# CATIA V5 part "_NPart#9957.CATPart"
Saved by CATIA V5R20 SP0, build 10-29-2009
Part number: Junta tórica Ø12x1
Revision: ANY
Definition: UNKNOWN
Nomenclature: Junta tórica Ø12x1
Source: Unknown
Bounding box of the stored display mesh (mm): x -6.824 to 6.824, y -0.5 to 0.5, z -7 to 7
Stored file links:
  C:\Users\Utente\Desktop\IO LAVORO\3D X SITO CF\CUMSA\3D files AE\AE 031620\_NPart#9957.CATPart
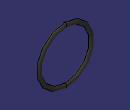
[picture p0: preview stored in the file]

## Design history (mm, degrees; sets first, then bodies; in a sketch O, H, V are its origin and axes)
Body1 "Revolución1" (main body)
  Solid1: solid without history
